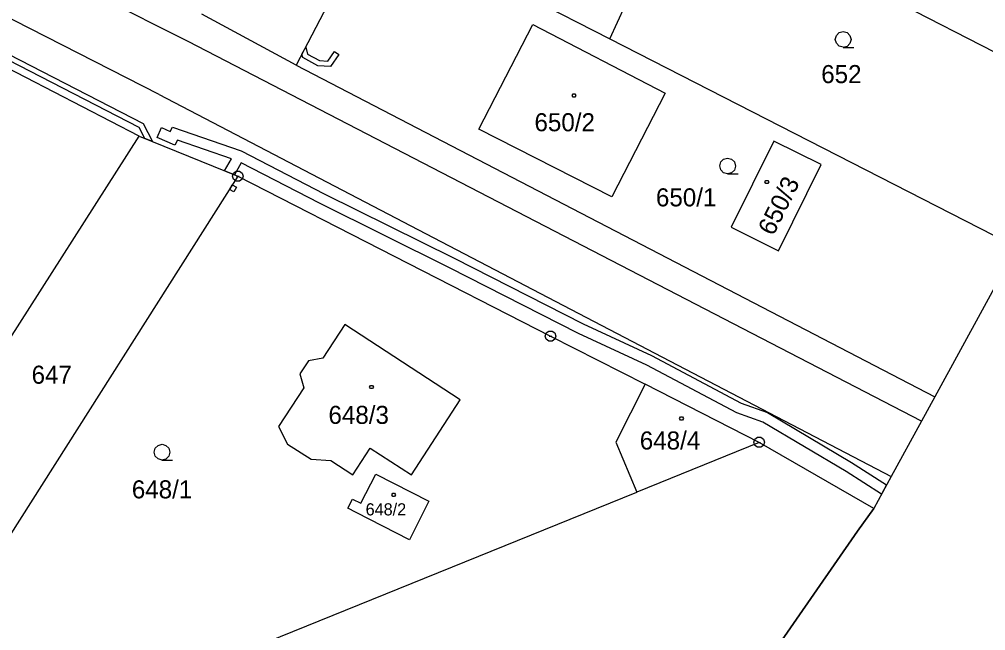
# Model space of a CAD drawing. Extents: x -759699 to -757730, y -1172308 to -1170857.
# Drawn here: x -758455.8 to -758364.9, y -1171396.5 to -1171339 of the extents above; entities that cross this region are included whole.
import ezdxf

# ---------------------------------------------------------------- set-up
doc = ezdxf.new("R2010")
doc.units = 0
for name, color, linetype in [('Vrstva 1', 7, 'Continuous'), ('Vrstva 11', 7, 'Continuous'), ('Vrstva 12', 7, 'Continuous'), ('Vrstva 13', 7, 'Continuous'), ('Vrstva 2', 7, 'Continuous'), ('Vrstva 3', 7, 'Continuous'), ('Vrstva 4', 7, 'Continuous'), ('Vrstva 5', 7, 'Continuous'), ('Vrstva 8', 7, 'Continuous')]:
    doc.layers.add(name, color=color, linetype=linetype)

msp = doc.modelspace()

# ---------------------------------------------------------------- linework, layer by layer
at = {"layer": 'Vrstva 1'}
for p, q in [((-758439.91, -1171341.05), (-758488.47, -1171316.61)), ((-758392.43, -1171327.41), (-758354.46, -1171346.98)), ((-758422.51, -1171329.39), (-758429.75, -1171343.26)), ((-758422.51, -1171329.39), (-758400.25, -1171340.79)), ((-758400.25, -1171340.79), (-758398.79, -1171337.64)), ((-758429.75, -1171343.26), (-758438.62, -1171338.48)), ((-758412.57, -1171349.28), (-758407.5, -1171339.43)), ((-758407.5, -1171339.43), (-758395.04, -1171345.91)), ((-758444.54, -1171349.94), (-758462.29, -1171340.76)), ((-758370.91, -1171376.78), (-758439.91, -1171341.05)), ((-758400.25, -1171340.79), (-758361.97, -1171360.38)), ((-758429.75, -1171343.26), (-758369.66, -1171374.49)), ((-758395.04, -1171345.91), (-758400.05, -1171355.65)), ((-758400.05, -1171355.65), (-758412.57, -1171349.28)), ((-758470.13, -1171390.04), (-758444.54, -1171349.94)), ((-758444.54, -1171349.94), (-758435.25, -1171353.72)), ((-758384.82, -1171350.41), (-758388.83, -1171358.53)), ((-758380.35, -1171352.62), (-758384.82, -1171350.41)), ((-758384.37, -1171360.74), (-758380.35, -1171352.62)), ((-758435.25, -1171353.72), (-758461.83, -1171395.59)), ((-758435.25, -1171353.72), (-758405.82, -1171368.77)), ((-758388.83, -1171358.53), (-758384.37, -1171360.74)), ((-758361.97, -1171360.38), (-758369.66, -1171374.49)), ((-758425.19, -1171367.69), (-758427.24, -1171370.84)), ((-758414.31, -1171374.76), (-758425.19, -1171367.69)), ((-758405.82, -1171368.77), (-758396.91, -1171373.3)), ((-758428.6, -1171371.09), (-758429.4, -1171372.33)), ((-758427.24, -1171370.84), (-758428.6, -1171371.09)), ((-758429.4, -1171372.33), (-758429.05, -1171373.63)), ((-758396.91, -1171373.3), (-758399.68, -1171378.75)), ((-758386.17, -1171378.77), (-758396.91, -1171373.3)), ((-758429.05, -1171373.63), (-758431.42, -1171377.27)), ((-758418.91, -1171381.83), (-758414.31, -1171374.76)), ((-758369.66, -1171374.49), (-758370.91, -1171376.78)), ((-758370.91, -1171376.78), (-758373.76, -1171381.98)), ((-758431.42, -1171377.27), (-758430.56, -1171378.93)), ((-758399.68, -1171378.75), (-758397.71, -1171383.44)), ((-758386.17, -1171378.77), (-758397.71, -1171383.44)), ((-758375.41, -1171384.98), (-758386.17, -1171378.77)), ((-758430.56, -1171378.93), (-758428.36, -1171380.36)), ((-758424.43, -1171381.81), (-758422.8, -1171379.3)), ((-758422.8, -1171379.3), (-758418.91, -1171381.83)), ((-758428.36, -1171380.36), (-758426.48, -1171380.48)), ((-758426.48, -1171380.48), (-758424.43, -1171381.81)), ((-758423.67, -1171384.5), (-758422.26, -1171381.75)), ((-758422.26, -1171381.75), (-758417.27, -1171384.29)), ((-758373.76, -1171381.98), (-758375.41, -1171384.98)), ((-758448.84, -1171404.15), (-758397.71, -1171383.44)), ((-758424.9, -1171384.97), (-758424.45, -1171384.1)), ((-758424.45, -1171384.1), (-758423.67, -1171384.5)), ((-758417.27, -1171384.29), (-758419.1, -1171387.93)), ((-758424.11, -1171385.37), (-758424.9, -1171384.97)), ((-758376.92, -1171387.14), (-758375.41, -1171384.98)), ((-758419.1, -1171387.93), (-758424.11, -1171385.37)), ((-758407.85, -1171431.61), (-758376.92, -1171387.14))]:
    msp.add_line(p, q, dxfattribs=at)
at = {"layer": 'Vrstva 11'}
for p, q in [((-758361.97, -1171360.38), (-758369.66, -1171374.49)), ((-758369.66, -1171374.49), (-758370.91, -1171376.78)), ((-758370.91, -1171376.78), (-758373.76, -1171381.98)), ((-758373.76, -1171381.98), (-758375.41, -1171384.98)), ((-758375.41, -1171384.98), (-758376.92, -1171387.14)), ((-758376.92, -1171387.14), (-758407.85, -1171431.61))]:
    msp.add_line(p, q, dxfattribs=at)
at = {"layer": 'Vrstva 12'}
for p, q in [((-758412.57, -1171349.28), (-758407.5, -1171339.43)), ((-758407.5, -1171339.43), (-758395.04, -1171345.91)), ((-758395.04, -1171345.91), (-758400.05, -1171355.65)), ((-758400.05, -1171355.65), (-758412.57, -1171349.28)), ((-758384.82, -1171350.41), (-758388.83, -1171358.53)), ((-758380.35, -1171352.62), (-758384.82, -1171350.41)), ((-758384.37, -1171360.74), (-758380.35, -1171352.62)), ((-758388.83, -1171358.53), (-758384.37, -1171360.74)), ((-758425.19, -1171367.69), (-758427.24, -1171370.84)), ((-758414.31, -1171374.76), (-758425.19, -1171367.69)), ((-758428.6, -1171371.09), (-758429.4, -1171372.33)), ((-758427.24, -1171370.84), (-758428.6, -1171371.09)), ((-758429.4, -1171372.33), (-758429.05, -1171373.63)), ((-758396.91, -1171373.3), (-758399.68, -1171378.75)), ((-758386.17, -1171378.77), (-758396.91, -1171373.3)), ((-758429.05, -1171373.63), (-758431.42, -1171377.27)), ((-758418.91, -1171381.83), (-758414.31, -1171374.76)), ((-758431.42, -1171377.27), (-758430.56, -1171378.93)), ((-758399.68, -1171378.75), (-758397.71, -1171383.44)), ((-758386.17, -1171378.77), (-758397.71, -1171383.44)), ((-758430.56, -1171378.93), (-758428.36, -1171380.36)), ((-758424.43, -1171381.81), (-758422.8, -1171379.3)), ((-758422.8, -1171379.3), (-758418.91, -1171381.83)), ((-758428.36, -1171380.36), (-758426.48, -1171380.48)), ((-758426.48, -1171380.48), (-758424.43, -1171381.81)), ((-758423.67, -1171384.5), (-758422.26, -1171381.75)), ((-758422.26, -1171381.75), (-758417.27, -1171384.29)), ((-758424.9, -1171384.97), (-758424.45, -1171384.1)), ((-758424.45, -1171384.1), (-758423.67, -1171384.5)), ((-758417.27, -1171384.29), (-758419.1, -1171387.93)), ((-758424.11, -1171385.37), (-758424.9, -1171384.97)), ((-758419.1, -1171387.93), (-758424.11, -1171385.37))]:
    msp.add_line(p, q, dxfattribs=at)
at = {"layer": 'Vrstva 13'}
for p, q in [((-758477.67, -1171331.47), (-758444.17, -1171348.77)), ((-758444.54, -1171349.14), (-758477.7, -1171332.02)), ((-758429.21, -1171342.23), (-758428.86, -1171341.56)), ((-758428.86, -1171341.56), (-758428.7, -1171342.22)), ((-758429.12, -1171342.56), (-758429.21, -1171342.23)), ((-758428.7, -1171342.22), (-758427.57, -1171342.84)), ((-758426.77, -1171342.89), (-758426.16, -1171341.99)), ((-758425.74, -1171342.26), (-758426.51, -1171343.41)), ((-758426.16, -1171341.99), (-758425.74, -1171342.26)), ((-758427.71, -1171343.34), (-758429.12, -1171342.56)), ((-758426.51, -1171343.41), (-758427.71, -1171343.34)), ((-758427.57, -1171342.84), (-758426.77, -1171342.89)), ((-758444.17, -1171348.77), (-758443.28, -1171350.45)), ((-758444, -1171350.16), (-758444.54, -1171349.14)), ((-758442.84, -1171350.07), (-758442.44, -1171349.15)), ((-758442.44, -1171349.15), (-758441.61, -1171349.51)), ((-758441.61, -1171349.51), (-758441.4, -1171349.11)), ((-758441.4, -1171349.11), (-758434.92, -1171351.34)), ((-758443.28, -1171350.45), (-758444, -1171350.16)), ((-758441.17, -1171350.79), (-758442.84, -1171350.07)), ((-758440.92, -1171350.33), (-758441.17, -1171350.79)), ((-758435.85, -1171352.08), (-758440.92, -1171350.33)), ((-758434.92, -1171351.34), (-758427.11, -1171355.37)), ((-758436.5, -1171353.21), (-758435.85, -1171352.08)), ((-758434.92, -1171352.47), (-758435.56, -1171353.59)), ((-758427.57, -1171356.27), (-758434.92, -1171352.47)), ((-758435.56, -1171353.59), (-758436.5, -1171353.21)), ((-758436.04, -1171354.96), (-758435.77, -1171354.54)), ((-758435.63, -1171355.19), (-758436.04, -1171354.96)), ((-758435.77, -1171354.54), (-758435.38, -1171354.75)), ((-758435.38, -1171354.75), (-758435.63, -1171355.19)), ((-758427.11, -1171355.37), (-758414.88, -1171361.43)), ((-758415.32, -1171362.33), (-758427.57, -1171356.27)), ((-758414.88, -1171361.43), (-758402.74, -1171367.62)), ((-758403.18, -1171368.52), (-758415.32, -1171362.33)), ((-758402.74, -1171367.62), (-758396.31, -1171370.6)), ((-758396.75, -1171371.5), (-758403.18, -1171368.52)), ((-758396.31, -1171370.6), (-758387.88, -1171375.08)), ((-758388.28, -1171376), (-758396.75, -1171371.5)), ((-758387.88, -1171375.08), (-758385.41, -1171375.96)), ((-758385.83, -1171376.86), (-758388.28, -1171376)), ((-758385.41, -1171375.96), (-758377.49, -1171380.65)), ((-758378.01, -1171381.51), (-758385.83, -1171376.86)), ((-758377.49, -1171380.65), (-758374.19, -1171382.77)), ((-758374.68, -1171383.64), (-758378.01, -1171381.51)), ((-758374.19, -1171382.77), (-758374.68, -1171383.64))]:
    msp.add_line(p, q, dxfattribs=at)
at = {"layer": 'Vrstva 3'}
for points in [[(-758378.27, -1171341.58), (-758378.65, -1171341.48), (-758378.92, -1171341.21), (-758379.02, -1171340.84), (-758378.92, -1171340.47), (-758378.65, -1171340.2), (-758378.28, -1171340.1), (-758377.91, -1171340.2), (-758377.64, -1171340.47), (-758377.54, -1171340.85), (-758377.64, -1171341.23), (-758377.91, -1171341.5), (-758378.29, -1171341.6), (-758377.29, -1171341.6)], [(-758389.15, -1171353.49), (-758389.53, -1171353.39), (-758389.8, -1171353.12), (-758389.9, -1171352.75), (-758389.8, -1171352.38), (-758389.53, -1171352.11), (-758389.16, -1171352.01), (-758388.79, -1171352.11), (-758388.52, -1171352.38), (-758388.42, -1171352.76), (-758388.52, -1171353.14), (-758388.79, -1171353.41), (-758389.17, -1171353.51), (-758388.17, -1171353.51)], [(-758442.37, -1171380.43), (-758442.75, -1171380.33), (-758443.02, -1171380.06), (-758443.12, -1171379.69), (-758443.02, -1171379.32), (-758442.75, -1171379.05), (-758442.38, -1171378.95), (-758442.01, -1171379.05), (-758441.74, -1171379.32), (-758441.64, -1171379.7), (-758441.74, -1171380.08), (-758442.01, -1171380.35), (-758442.39, -1171380.45), (-758441.39, -1171380.45)]]:
    msp.add_lwpolyline(points, dxfattribs=at)
at = {"layer": 'Vrstva 4'}
for q in [(-758490.86, -1171321.53), (-758373.76, -1171381.98)]:
    msp.add_line((-758442.66, -1171346.03), q, dxfattribs=at)
at = {"layer": 'Vrstva 5'}
for points in [[(-758403.52, -1171345.97), (-758403.43, -1171346.12), (-758403.52, -1171346.27), (-758403.7, -1171346.27), (-758403.79, -1171346.12), (-758403.7, -1171345.97)], [(-758385.38, -1171354.11), (-758385.29, -1171354.26), (-758385.38, -1171354.41), (-758385.56, -1171354.41), (-758385.65, -1171354.26), (-758385.56, -1171354.11)], [(-758422.58, -1171373.41), (-758422.49, -1171373.56), (-758422.58, -1171373.71), (-758422.76, -1171373.71), (-758422.85, -1171373.56), (-758422.76, -1171373.41)], [(-758393.41, -1171376.37), (-758393.32, -1171376.52), (-758393.41, -1171376.67), (-758393.59, -1171376.67), (-758393.68, -1171376.52), (-758393.59, -1171376.37)], [(-758420.49, -1171383.56), (-758420.4, -1171383.71), (-758420.49, -1171383.86), (-758420.67, -1171383.86), (-758420.76, -1171383.71), (-758420.67, -1171383.56)]]:
    msp.add_lwpolyline(points, close=True, dxfattribs=at)
at = {"layer": 'Vrstva 8'}
for p, q in [((-758435.37, -1171353.72), (-758435.13, -1171353.72)), ((-758405.94, -1171368.77), (-758405.7, -1171368.77)), ((-758386.29, -1171378.77), (-758386.05, -1171378.77))]:
    msp.add_line(p, q, dxfattribs=at)
for points in [[(-758435.1, -1171353.24), (-758434.85, -1171353.42), (-758434.75, -1171353.71), (-758434.85, -1171354), (-758435.1, -1171354.18), (-758435.41, -1171354.18), (-758435.66, -1171354), (-758435.76, -1171353.71), (-758435.66, -1171353.42), (-758435.41, -1171353.24)], [(-758405.67, -1171368.29), (-758405.42, -1171368.47), (-758405.32, -1171368.76), (-758405.42, -1171369.05), (-758405.67, -1171369.23), (-758405.98, -1171369.23), (-758406.23, -1171369.05), (-758406.33, -1171368.76), (-758406.23, -1171368.47), (-758405.98, -1171368.29)], [(-758386.02, -1171378.29), (-758385.77, -1171378.47), (-758385.67, -1171378.76), (-758385.77, -1171379.05), (-758386.02, -1171379.23), (-758386.33, -1171379.23), (-758386.58, -1171379.05), (-758386.68, -1171378.76), (-758386.58, -1171378.47), (-758386.33, -1171378.29)]]:
    msp.add_lwpolyline(points, close=True, dxfattribs=at)

# ---------------------------------------------------------------- texts
at = {"layer": 'Vrstva 2'}
for s, height, p in [('652', 1.7, (-758380.345, -1171344.96)), ('650/2', 1.7, (-758407.33, -1171349.49)), ('650/1', 1.7, (-758395.899, -1171356.56)), ('647', 1.7, (-758454.654, -1171373.25)), ('648/3', 1.7, (-758426.717, -1171377.03)), ('648/4', 1.7, (-758397.42, -1171379.44)), ('648/1', 1.7, (-758445.222, -1171384.04)), ('648/2', 1.14, (-758423.22, -1171385.64))]:
    msp.add_text(s, height=height, dxfattribs=at).set_placement(p)
msp.add_text('650/3', height=1.7, rotation=63.65561, dxfattribs=at).set_placement((-758384.855, -1171359.411))

doc.saveas('drawing.dxf')
